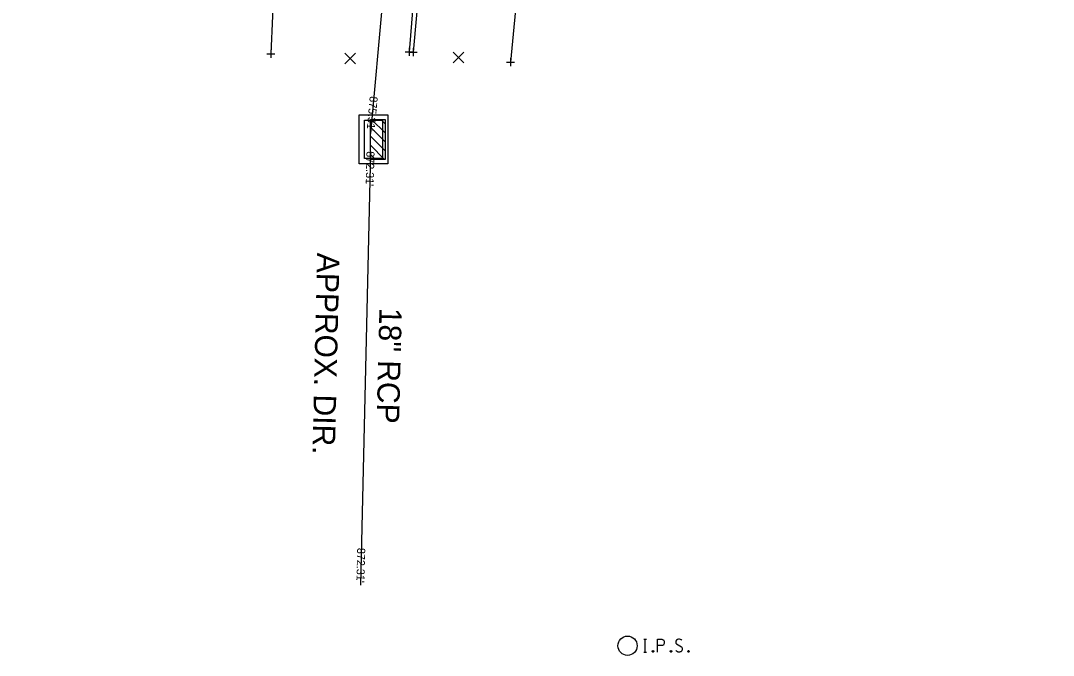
# Model space of a CAD drawing. Extents: x 1380550 to 1381945, y 468927 to 470496.
# Drawn here: x 1381457 to 1381586, y 468927.3 to 469006.5 of the extents above; entities that cross this region are included whole.
import ezdxf

# ---------------------------------------------------------------- set-up
doc = ezdxf.new("R2010")
doc.units = 0
for name, color, linetype in [('DR_X_Cells', 7, 'Continuous'), ('DR_X_Storm_Sewer', 7, 'Continuous'), ('DR_X_Text', 7, 'Continuous'), ('GK_Drainage_Nodes', 7, 'Continuous'), ('PV_X_COP', 7, 'Continuous'), ('PV_X_Curb', 7, 'Continuous'), ('PV_X_EOP', 7, 'Continuous'), ('RD_X_Fence', 7, 'Continuous'), ('SC_Scratch1', 7, 'Continuous'), ('SV_P_Mon_Cells_Set', 7, 'Continuous'), ('SV_X_Random_Point', 7, 'Continuous'), ('SV_X_Shot_Marker', 7, 'Continuous')]:
    doc.layers.add(name, color=color, linetype=linetype)

msp = doc.modelspace()

# ---------------------------------------------------------------- linework, layer by layer
at = {"layer": 'DR_X_Cells'}
for p, q in [((1381502.54, 468991.35), (1381500.71, 468993.18)), ((1381502.54, 468992.48), (1381500.85, 468994.16)), ((1381502.54, 468993.61), (1381501.98, 468994.16)), ((1381502.54, 468990.22), (1381500.71, 468992.05)), ((1381502.47, 468989.16), (1381500.71, 468990.92)), ((1381501.33, 468989.16), (1381500.71, 468989.79))]:
    msp.add_line(p, q, dxfattribs=at)
for points in [[(1381499.29, 468988.62), (1381499.29, 468994.71), (1381502.87, 468994.71), (1381502.87, 468988.62)], [(1381499.96, 468989.29), (1381499.96, 468994.04), (1381502.21, 468994.04), (1381502.21, 468989.29)], [(1381500.71, 468989.16), (1381500.71, 468994.16), (1381502.54, 468994.16), (1381502.54, 468989.16)]]:
    msp.add_lwpolyline(points, close=True, dxfattribs=at)
at = {"layer": 'DR_X_Storm_Sewer'}
for p, q in [((1381528.04, 469296.45), (1381500.71, 468992.41)), ((1381500.71, 468990.16), (1381499.44, 468936.03))]:
    msp.add_line(p, q, dxfattribs=at)
at = {"layer": 'GK_Drainage_Nodes'}
for p, q in [((1381501.08, 468994.04), (1381501.08, 468994.04)), ((1381499.29, 468991.66), (1381499.29, 468991.66)), ((1381499.96, 468991.66), (1381499.96, 468991.66)), ((1381500.71, 468991.66), (1381500.71, 468991.66)), ((1381500.71, 468991.66), (1381500.71, 468991.66)), ((1381501.08, 468991.66), (1381501.08, 468991.66)), ((1381502.21, 468991.66), (1381502.21, 468991.66)), ((1381502.87, 468991.66), (1381502.87, 468991.66)), ((1381501.08, 468989.29), (1381501.08, 468989.29))]:
    msp.add_line(p, q, dxfattribs=at)
at = {"layer": 'PV_X_COP'}
msp.add_lwpolyline([(1381585.99, 469815.58), (1381581.29, 469760.78), (1381580.3, 469747.86), (1381578.72, 469729.45), (1381576.78, 469708.95), (1381575.29, 469689.79), (1381572.76, 469657.56), (1381569.36, 469615.7), (1381565.36, 469567.23), (1381561.16, 469537.52), (1381558.94, 469486.81), (1381555.39, 469442.03), (1381550.97, 469391.02), (1381547.28, 469345.9), (1381541.95, 469289.55), (1381537.19, 469231.27), (1381533.05, 469168.09), (1381530.32, 469133.74), (1381523.97, 469065.08), (1381520.12, 469021.37), (1381518.18, 469001.31)], dxfattribs=at)
at = {"layer": 'PV_X_Curb'}
msp.add_lwpolyline([(1381507.02, 469023.6), (1381507.17, 469022.55), (1381505.52, 469002.58)], dxfattribs=at)
at = {"layer": 'PV_X_EOP'}
msp.add_lwpolyline([(1381521.19, 469168.77), (1381520.16, 469156.66), (1381518.94, 469140.36), (1381518.51, 469135.77), (1381515.95, 469110.14), (1381515.91, 469109.22), (1381513.99, 469088.5), (1381512.04, 469066.8), (1381509.95, 469044.61), (1381509.76, 469043.72), (1381507.94, 469023.87), (1381507.81, 469022.45), (1381506.02, 469002.56)], dxfattribs=at)
at = {"layer": 'RD_X_Fence'}
msp.add_lwpolyline([(1381457.02, 469027.67), (1381476.99, 469026.56), (1381489.32, 469026.11), (1381488.25, 469002.32)], dxfattribs=at)
at = {"layer": 'SV_P_Mon_Cells_Set'}
for points in [[(1381534.83, 468929.27), (1381535.18, 468929.27)], [(1381535, 468927.67), (1381535, 468929.27)], [(1381536.57, 468927.67), (1381536.57, 468929.27), (1381537.1, 468929.27), (1381537.15, 468929.26), (1381537.23, 468929.24), (1381537.26, 468929.21), (1381537.3, 468929.19), (1381537.34, 468929.12), (1381537.37, 468929.06), (1381537.4, 468928.96), (1381537.4, 468928.81), (1381537.39, 468928.76), (1381537.36, 468928.68), (1381537.32, 468928.59), (1381537.28, 468928.56), (1381537.24, 468928.53), (1381537.19, 468928.5), (1381537.1, 468928.49), (1381536.57, 468928.49)], [(1381539.58, 468929.16), (1381539.56, 468929.19), (1381539.52, 468929.21), (1381539.42, 468929.25), (1381539.3, 468929.27), (1381539.22, 468929.27), (1381539.18, 468929.27), (1381539.04, 468929.24), (1381538.92, 468929.16), (1381538.84, 468929.06), (1381538.82, 468928.96), (1381538.82, 468928.88), (1381538.84, 468928.78), (1381538.93, 468928.69), (1381539.53, 468928.32), (1381539.59, 468928.27), (1381539.61, 468928.22), (1381539.63, 468928.14), (1381539.63, 468928.06), (1381539.62, 468927.99), (1381539.61, 468927.94), (1381539.59, 468927.87), (1381539.57, 468927.82), (1381539.55, 468927.79), (1381539.51, 468927.75), (1381539.48, 468927.72), (1381539.44, 468927.7), (1381539.4, 468927.69), (1381539.3, 468927.67), (1381539.15, 468927.67), (1381539.05, 468927.7), (1381538.91, 468927.79), (1381538.82, 468927.86)], [(1381534.83, 468927.67), (1381535.18, 468927.67)], [(1381535.96, 468927.89), (1381536.02, 468927.89), (1381536.05, 468927.86), (1381536.08, 468927.81), (1381536.08, 468927.75), (1381536.05, 468927.7), (1381536.02, 468927.67), (1381535.96, 468927.67), (1381535.93, 468927.7), (1381535.9, 468927.75), (1381535.9, 468927.81), (1381535.93, 468927.86), (1381535.96, 468927.89)], [(1381538.21, 468927.89), (1381538.27, 468927.89), (1381538.3, 468927.86), (1381538.33, 468927.81), (1381538.33, 468927.75), (1381538.3, 468927.7), (1381538.27, 468927.67), (1381538.21, 468927.67), (1381538.18, 468927.7), (1381538.15, 468927.75), (1381538.15, 468927.81), (1381538.18, 468927.86), (1381538.21, 468927.89)], [(1381540.39, 468927.89), (1381540.45, 468927.89), (1381540.48, 468927.86), (1381540.52, 468927.81), (1381540.52, 468927.75), (1381540.48, 468927.7), (1381540.45, 468927.67), (1381540.39, 468927.67), (1381540.36, 468927.7), (1381540.33, 468927.75), (1381540.33, 468927.81), (1381540.36, 468927.86), (1381540.39, 468927.89)]]:
    msp.add_lwpolyline(points, dxfattribs=at)
msp.add_circle((1381532.81, 468928.47), 1.2, dxfattribs=at)
at = {"layer": 'SV_X_Random_Point'}
for p, q in [((1381497.51, 469001.09), (1381498.84, 469002.42)), ((1381497.51, 469002.42), (1381498.84, 469001.09)), ((1381511.04, 469001.23), (1381512.38, 469002.56)), ((1381511.04, 469002.56), (1381512.38, 469001.23))]:
    msp.add_line(p, q, dxfattribs=at)
at = {"layer": 'SV_X_Shot_Marker'}
for p, q in [((1381487.75, 469002.32), (1381488.75, 469002.32)), ((1381488.25, 469002.82), (1381488.25, 469001.82)), ((1381488.25, 469002.32), (1381488.25, 469002.32)), ((1381505.02, 469002.58), (1381506.02, 469002.58)), ((1381505.52, 469003.08), (1381505.52, 469002.08)), ((1381505.52, 469002.58), (1381505.52, 469002.58)), ((1381505.52, 469002.56), (1381506.52, 469002.56)), ((1381506.02, 469003.06), (1381506.02, 469002.06)), ((1381506.02, 469002.56), (1381506.02, 469002.56)), ((1381517.68, 469001.31), (1381518.68, 469001.31)), ((1381518.18, 469001.81), (1381518.18, 469000.81)), ((1381518.18, 469001.31), (1381518.18, 469001.31))]:
    msp.add_line(p, q, dxfattribs=at)

# ---------------------------------------------------------------- texts
at = {"layer": 'DR_X_Text'}
for s, p in [('APPROX. DIR.', (1381494.05, 468977.53)), ('18" RCP', (1381501.82, 468970.66))]:
    msp.add_text(s, height=2.8, rotation=268.6571, dxfattribs=at).set_placement(p)
at = {"layer": 'SC_Scratch1'}
for s, rotation, p in [("875.31'", 264.8634, (1381500.62, 468997.07)), ("872.31'", 268.6571, (1381500.21, 468990.18)), ("872.31'", 268.6571, (1381499.05, 468940.68))]:
    msp.add_text(s, height=1, rotation=rotation, dxfattribs=at).set_placement(p)

doc.saveas('drawing.dxf')
